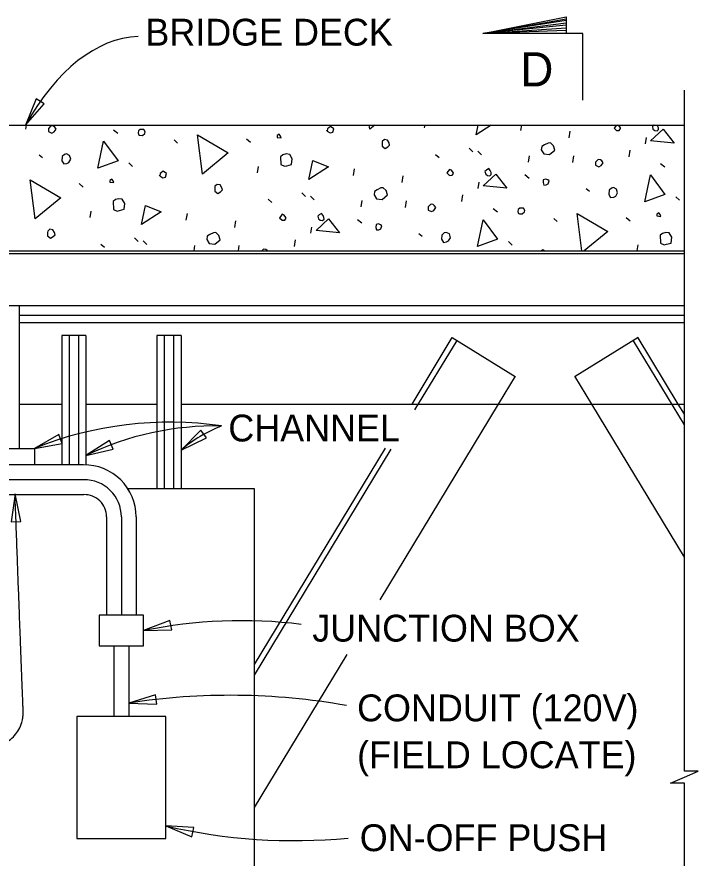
# Model space of a CAD drawing. Extents: x 927736.2 to 927809.6, y 636703.6 to 636757.7.
# Drawn here: x 927764.73 to 927774.19, y 636721.33 to 636733.02 of the extents above; entities that cross this region are included whole.
import ezdxf

# ---------------------------------------------------------------- set-up
doc = ezdxf.new("R2010")
doc.units = 0
for name, color, linetype in [('DimLines_dp', 7, 'Continuous'), ('Miscellaneous1', 7, 'Continuous'), ('Miscellaneous2', 7, 'Continuous'), ('Miscellaneous3', 7, 'Continuous')]:
    doc.layers.add(name, color=color, linetype=linetype)

msp = doc.modelspace()

# ---------------------------------------------------------------- linework, layer by layer
at = {"layer": 'DimLines_dp'}
for p, q in [((927771.201, 636732.786), (927772.357, 636732.99)), ((927772.357, 636732.965), (927771.201, 636732.786)), ((927771.201, 636732.786), (927772.357, 636732.934)), ((927772.357, 636732.901), (927771.201, 636732.786)), ((927771.201, 636732.786), (927772.357, 636732.867)), ((927772.357, 636732.83), (927771.201, 636732.786))]:
    msp.add_line(p, q, dxfattribs=at)
for points in [[(927772.589, 636731.861), (927772.589, 636732.786), (927771.201, 636732.786), (927772.357, 636733.018), (927772.357, 636732.786)], [(927774, 636713.104), (927774, 636722.378), (927773.809, 636722.378), (927774, 636722.461), (927774.191, 636722.544), (927774, 636722.544), (927774, 636731.999)]]:
    msp.add_lwpolyline(points, dxfattribs=at)
for points in [[(927764.852, 636731.515), (927765.11, 636731.808), (927764.999, 636731.877)], [(927767.01, 636727), (927767.362, 636727.17), (927767.286, 636727.277)], [(927764.974, 636727.024), (927765.359, 636727.094), (927765.315, 636727.216)], [(927765.688, 636726.926), (927766.068, 636727.016), (927766.018, 636727.136)], [(927764.705, 636726.393), (927764.654, 636726.006), (927764.785, 636726.011)], [(927766.491, 636724.495), (927766.881, 636724.507), (927766.855, 636724.635)], [(927766.285, 636723.488), (927766.675, 636723.474), (927766.658, 636723.603)], [(927766.799, 636721.782), (927767.159, 636721.632), (927767.189, 636721.759)]]:
    msp.add_lwpolyline(points, close=True, dxfattribs=at)
for centre, radius, start, end in [((927766.848, 636722.389), 5, 81.6635, 112.0069), ((927767.492, 636723.175), 4.162, 88.8828, 115.6789), ((927768.324, 636725.436), 2.043, 111.5678, 130.0212), ((927767.852, 636717.791), 6.841, 83.0445, 101.4782), ((927767.692, 636714.325), 9.271, 79.9649, 98.7311), ((927768.59, 636729.517), 7.939, 256.9627, 275.3449)]:
    msp.add_arc(centre, radius, start, end, dxfattribs=at)
msp.add_ellipse((927766.69, 636726.905), major_axis=(0.274, -5.84), ratio=0.464296, start_param=3.141604, end_param=3.781059, dxfattribs=at)
msp.add_open_spline([(927758.883, 636722.628), (927762.516, 636722.653), (927764.844, 636722.779), (927764.793, 636724), (927764.705, 636726.393)], degree=2, dxfattribs=at)
at = {"layer": 'Miscellaneous1'}
for p, q in [((927765.354, 636728.592), (927765.354, 636726.795)), ((927765.688, 636728.592), (927765.354, 636728.592)), ((927765.457, 636728.592), (927765.457, 636726.795)), ((927765.586, 636728.592), (927765.586, 636726.795)), ((927765.688, 636728.592), (927765.688, 636726.795)), ((927767.01, 636728.592), (927766.676, 636728.592)), ((927766.676, 636728.592), (927766.676, 636726.463)), ((927766.778, 636728.592), (927766.778, 636726.463)), ((927766.907, 636728.592), (927766.907, 636726.463)), ((927767.01, 636728.592), (927767.01, 636726.463)), ((927764.139, 636727.024), (927764.974, 636727.024)), ((927764.974, 636727.024), (927764.974, 636726.795)), ((927765.656, 636726.795), (927764.242, 636726.795)), ((927765.66, 636726.589), (927764.242, 636726.59)), ((927764.242, 636726.384), (927765.662, 636726.383)), ((927765.976, 636726.075), (927765.976, 636724.707)), ((927766.182, 636726.075), (927766.182, 636724.707)), ((927766.388, 636726.075), (927766.388, 636724.707)), ((927766.079, 636724.283), (927766.079, 636723.302)), ((927766.285, 636724.283), (927766.285, 636723.302))]:
    msp.add_line(p, q, dxfattribs=at)
for points in [[(927766.49, 636724.707), (927765.874, 636724.707), (927765.874, 636724.283), (927766.49, 636724.283)], [(927766.799, 636723.302), (927765.565, 636723.302), (927765.565, 636721.607), (927766.799, 636721.607)]]:
    msp.add_lwpolyline(points, close=True, dxfattribs=at)
for radius, end in [(0.72, 90.9434), (0.514, 90.8699), (0.308, 91.129)]:
    msp.add_arc((927765.668, 636726.075), radius, 0, end, dxfattribs=at)
at = {"layer": 'Miscellaneous2'}
for p, q in [((927753.063, 636731.515), (927774, 636731.515)), ((927764.855, 636731.46), (927764.863, 636731.515)), ((927770.393, 636731.476), (927770.399, 636731.515)), ((927771.731, 636731.438), (927771.742, 636731.515)), ((927766.072, 636731.448), (927766.135, 636731.401)), ((927772.402, 636731.337), (927772.416, 636731.43)), ((927773.458, 636731.256), (927773.473, 636731.343)), ((927766.913, 636731.309), (927766.963, 636731.265)), ((927767.918, 636731.323), (927767.976, 636731.275)), ((927765.041, 636731.101), (927765.089, 636731.063)), ((927770.542, 636731.107), (927770.593, 636731.063)), ((927771.011, 636731.194), (927771.062, 636731.144)), ((927771.131, 636731.15), (927771.183, 636731.1)), ((927773.232, 636731.075), (927773.246, 636731.168)), ((927766.284, 636730.988), (927766.336, 636730.938)), ((927771.835, 636731), (927771.85, 636731.087)), ((927772.45, 636730.993), (927772.463, 636731.086)), ((927768.07, 636730.853), (927768.085, 636730.94)), ((927769.407, 636730.816), (927769.421, 636730.909)), ((927773.666, 636730.98), (927773.73, 636730.933)), ((927770.079, 636730.715), (927770.093, 636730.808)), ((927771.786, 636730.827), (927771.843, 636730.779)), ((927765.595, 636730.701), (927765.653, 636730.652)), ((927771.135, 636730.634), (927771.15, 636730.721)), ((927772.636, 636730.634), (927772.684, 636730.596)), ((927768.688, 636730.572), (927768.739, 636730.522)), ((927768.808, 636730.528), (927768.86, 636730.478)), ((927770.909, 636730.452), (927770.923, 636730.545)), ((927773.879, 636730.52), (927773.931, 636730.47)), ((927768.219, 636730.485), (927768.269, 636730.441)), ((927769.512, 636730.378), (927769.527, 636730.465)), ((927770.127, 636730.37), (927770.14, 636730.463)), ((927765.747, 636730.231), (927765.762, 636730.318)), ((927767.084, 636730.193), (927767.098, 636730.286)), ((927771.343, 636730.358), (927771.407, 636730.311)), ((927767.756, 636730.092), (927767.77, 636730.185)), ((927769.463, 636730.205), (927769.52, 636730.157)), ((927772.185, 636730.219), (927772.235, 636730.175)), ((927773.19, 636730.233), (927773.247, 636730.185)), ((927768.812, 636730.012), (927768.827, 636730.099)), ((927766.365, 636729.949), (927766.416, 636729.899)), ((927770.313, 636730.011), (927770.361, 636729.973)), ((927765.896, 636729.862), (927765.946, 636729.818)), ((927766.485, 636729.905), (927766.537, 636729.855)), ((927767.191, 636729.768), (927767.204, 636729.842)), ((927767.807, 636729.768), (927767.817, 636729.841)), ((927768.586, 636729.83), (927768.6, 636729.923)), ((927771.556, 636729.898), (927771.608, 636729.848)), ((927773.342, 636729.768), (927773.356, 636729.85)), ((927762.11, 636729.768), (927774, 636729.768)), ((927762.121, 636729.73), (927774, 636729.73)), ((927760.453, 636729.01), (927774, 636729.01))]:
    msp.add_line(p, q, dxfattribs=at)
for points in [[(927765.172, 636731.469), (927765.171, 636731.424), (927765.215, 636731.403), (927765.249, 636731.419), (927765.277, 636731.458), (927765.257, 636731.485), (927765.241, 636731.5), (927765.213, 636731.505), (927765.202, 636731.502), (927765.172, 636731.469)], [(927766.421, 636731.382), (927766.436, 636731.373), (927766.475, 636731.371), (927766.506, 636731.398), (927766.513, 636731.419), (927766.492, 636731.452), (927766.441, 636731.451), (927766.42, 636731.433), (927766.415, 636731.406), (927766.421, 636731.382)], [(927769.038, 636731.432), (927769.083, 636731.406), (927769.119, 636731.415), (927769.132, 636731.463), (927769.085, 636731.495), (927769.064, 636731.477), (927769.042, 636731.465), (927769.038, 636731.432), (927769.035, 636731.444)], [(927769.632, 636731.457), (927769.624, 636731.515)], [(927769.702, 636731.515), (927769.632, 636731.457)], [(927771.108, 636731.38), (927771.137, 636731.515)], [(927771.318, 636731.515), (927771.108, 636731.38)], [(927773.024, 636731.472), (927773.059, 636731.437), (927773.096, 636731.44), (927773.115, 636731.465), (927773.112, 636731.476), (927773.091, 636731.509), (927773.075, 636731.515)], [(927773.058, 636731.515), (927773.043, 636731.496), (927773.024, 636731.472)], [(927773.531, 636731.295), (927773.705, 636731.457), (927773.859, 636731.262), (927773.531, 636731.295)], [(927773.581, 636731.515), (927773.575, 636731.511), (927773.555, 636731.493), (927773.564, 636731.457)], [(927773.564, 636731.457), (927773.588, 636731.438), (927773.621, 636731.434), (927773.642, 636731.452), (927773.642, 636731.478), (927773.628, 636731.506), (927773.621, 636731.515)], [(927767.308, 636730.834), (927767.24, 636731.378), (927767.664, 636731.128), (927767.308, 636730.834)], [(927768.347, 636731.342), (927768.399, 636731.337), (927768.393, 636731.361), (927768.373, 636731.388), (927768.347, 636731.368), (927768.347, 636731.342)], [(927765.856, 636730.918), (927765.935, 636731.29), (927766.136, 636731.018), (927765.856, 636730.918)], [(927769.804, 636731.267), (927769.803, 636731.222), (927769.844, 636731.188), (927769.882, 636731.211), (927769.907, 636731.237), (927769.9, 636731.267), (927769.876, 636731.305), (927769.836, 636731.314), (927769.805, 636731.286), (927769.804, 636731.267)], [(927772.013, 636731.169), (927772.047, 636731.115), (927772.127, 636731.104), (927772.199, 636731.168), (927772.183, 636731.228), (927772.14, 636731.267), (927772.109, 636731.265), (927772.058, 636731.239), (927772.02, 636731.216), (927772.013, 636731.169)], [(927765.36, 636731.078), (927765.356, 636731.02), (927765.381, 636730.975), (927765.424, 636730.981), (927765.452, 636730.995), (927765.479, 636731.04), (927765.464, 636731.094), (927765.421, 636731.114), (927765.391, 636731.106), (927765.36, 636731.078)], [(927768.393, 636731.074), (927768.397, 636730.966), (927768.448, 636730.942), (927768.478, 636730.95), (927768.543, 636730.967), (927768.554, 636731.047), (927768.519, 636731.108), (927768.472, 636731.114), (927768.424, 636731.101), (927768.393, 636731.074)], [(927768.785, 636730.757), (927768.842, 636731.022), (927769.057, 636730.933), (927768.785, 636730.757)], [(927772.767, 636731.001), (927772.766, 636730.956), (927772.81, 636730.936), (927772.844, 636730.951), (927772.872, 636730.991), (927772.852, 636731.017), (927772.835, 636731.032), (927772.808, 636731.038), (927772.796, 636731.034), (927772.767, 636731.001)], [(927766.715, 636730.809), (927766.76, 636730.783), (927766.796, 636730.793), (927766.809, 636730.841), (927766.762, 636730.873), (927766.741, 636730.855), (927766.719, 636730.842), (927766.715, 636730.809), (927766.712, 636730.821)], [(927770.701, 636730.85), (927770.736, 636730.814), (927770.773, 636730.818), (927770.792, 636730.842), (927770.789, 636730.854), (927770.768, 636730.887), (927770.739, 636730.898), (927770.72, 636730.874), (927770.701, 636730.85)], [(927771.241, 636730.835), (927771.265, 636730.816), (927771.298, 636730.812), (927771.319, 636730.83), (927771.319, 636730.855), (927771.305, 636730.884), (927771.285, 636730.91), (927771.252, 636730.889), (927771.231, 636730.87), (927771.241, 636730.835)], [(927764.985, 636730.212), (927764.916, 636730.755), (927765.341, 636730.505), (927764.985, 636730.212)], [(927766.024, 636730.72), (927766.076, 636730.715), (927766.07, 636730.739), (927766.05, 636730.765), (927766.024, 636730.745), (927766.024, 636730.72)], [(927771.208, 636730.673), (927771.382, 636730.834), (927771.536, 636730.639), (927771.208, 636730.673)], [(927772.039, 636730.716), (927772.048, 636730.681), (927772.08, 636730.683), (927772.108, 636730.697), (927772.122, 636730.739), (927772.106, 636730.754), (927772.077, 636730.765), (927772.041, 636730.755), (927772.039, 636730.716)], [(927773.451, 636730.45), (927773.53, 636730.822), (927773.73, 636730.55), (927773.451, 636730.45)], [(927767.481, 636730.644), (927767.48, 636730.599), (927767.521, 636730.566), (927767.559, 636730.589), (927767.584, 636730.615), (927767.576, 636730.644), (927767.553, 636730.683), (927767.513, 636730.691), (927767.482, 636730.664), (927767.481, 636730.644)], [(927769.69, 636730.547), (927769.724, 636730.492), (927769.804, 636730.481), (927769.876, 636730.545), (927769.86, 636730.605), (927769.817, 636730.645), (927769.786, 636730.643), (927769.735, 636730.616), (927769.697, 636730.593), (927769.69, 636730.547)], [(927772.955, 636730.611), (927772.951, 636730.552), (927772.976, 636730.508), (927773.019, 636730.513), (927773.047, 636730.527), (927773.073, 636730.572), (927773.059, 636730.626), (927773.015, 636730.646), (927772.986, 636730.638), (927772.955, 636730.611)], [(927766.07, 636730.452), (927766.074, 636730.344), (927766.125, 636730.319), (927766.155, 636730.327), (927766.22, 636730.345), (927766.231, 636730.424), (927766.195, 636730.485), (927766.149, 636730.492), (927766.101, 636730.479), (927766.07, 636730.452)], [(927766.462, 636730.135), (927766.519, 636730.399), (927766.734, 636730.31), (927766.462, 636730.135)], [(927770.444, 636730.379), (927770.443, 636730.334), (927770.487, 636730.313), (927770.521, 636730.329), (927770.549, 636730.368), (927770.529, 636730.395), (927770.512, 636730.41), (927770.485, 636730.415), (927770.473, 636730.412), (927770.444, 636730.379)], [(927768.918, 636730.212), (927768.942, 636730.193), (927768.975, 636730.189), (927768.996, 636730.208), (927768.995, 636730.233), (927768.982, 636730.261), (927768.962, 636730.288), (927768.929, 636730.266), (927768.908, 636730.248), (927768.918, 636730.212)], [(927771.693, 636730.292), (927771.708, 636730.283), (927771.747, 636730.281), (927771.778, 636730.308), (927771.785, 636730.329), (927771.764, 636730.362), (927771.713, 636730.361), (927771.692, 636730.343), (927771.687, 636730.316), (927771.693, 636730.292)], [(927772.577, 636729.768), (927772.511, 636730.288), (927772.936, 636730.038), (927772.609, 636729.768)], [(927773.619, 636730.252), (927773.671, 636730.247), (927773.665, 636730.271), (927773.645, 636730.298), (927773.618, 636730.278), (927773.619, 636730.252)], [(927768.378, 636730.227), (927768.413, 636730.192), (927768.45, 636730.195), (927768.469, 636730.22), (927768.466, 636730.232), (927768.444, 636730.264), (927768.416, 636730.276), (927768.397, 636730.251), (927768.378, 636730.227)], [(927768.885, 636730.05), (927769.059, 636730.212), (927769.213, 636730.017), (927768.885, 636730.05)], [(927771.128, 636729.828), (927771.207, 636730.2), (927771.407, 636729.928), (927771.128, 636729.828)], [(927765.158, 636730.022), (927765.157, 636729.977), (927765.198, 636729.943), (927765.236, 636729.966), (927765.261, 636729.992), (927765.253, 636730.022), (927765.23, 636730.06), (927765.19, 636730.069), (927765.159, 636730.041), (927765.158, 636730.022)], [(927769.716, 636730.094), (927769.725, 636730.058), (927769.757, 636730.06), (927769.785, 636730.074), (927769.799, 636730.116), (927769.782, 636730.131), (927769.754, 636730.143), (927769.718, 636730.133), (927769.716, 636730.094)], [(927767.367, 636729.924), (927767.401, 636729.87), (927767.48, 636729.859), (927767.553, 636729.923), (927767.537, 636729.983), (927767.494, 636730.022), (927767.463, 636730.02), (927767.412, 636729.994), (927767.374, 636729.971), (927767.367, 636729.924)], [(927770.632, 636729.988), (927770.628, 636729.93), (927770.653, 636729.885), (927770.696, 636729.891), (927770.724, 636729.905), (927770.75, 636729.95), (927770.736, 636730.003), (927770.692, 636730.024), (927770.662, 636730.016), (927770.632, 636729.988)], [(927773.665, 636729.984), (927773.669, 636729.876), (927773.72, 636729.852), (927773.75, 636729.86), (927773.815, 636729.877), (927773.826, 636729.957), (927773.79, 636730.017), (927773.744, 636730.024), (927773.696, 636730.011), (927773.665, 636729.984)], [(927768.209, 636729.768), (927768.206, 636729.772), (927768.189, 636729.787), (927768.162, 636729.793), (927768.15, 636729.789), (927768.132, 636729.768)], [(927772.055, 636729.768), (927772.034, 636729.783), (927772.017, 636729.768)]]:
    msp.add_lwpolyline(points, dxfattribs=at)
at = {"layer": 'Miscellaneous3'}
for p, q in [((927764.769, 636727.024), (927764.769, 636729.01)), ((927764.769, 636728.875), (927774, 636728.875)), ((927764.769, 636728.772), (927774, 636728.772)), ((927770.219, 636727.641), (927770.777, 636728.564)), ((927770.777, 636728.564), (927771.65, 636728.021)), ((927773.356, 636728.564), (927772.483, 636728.021)), ((927773.915, 636727.641), (927773.36, 636728.559)), ((927770.259, 636727.559), (927770.843, 636728.524)), ((927774, 636727.351), (927773.294, 636728.519)), ((927771.42, 636727.641), (927771.654, 636728.027)), ((927772.713, 636727.641), (927772.48, 636728.027)), ((927764.769, 636727.641), (927765.354, 636727.641)), ((927765.688, 636727.641), (927766.676, 636727.641)), ((927767.01, 636727.641), (927774, 636727.641)), ((927769.775, 636724.921), (927771.42, 636727.641)), ((927774, 636725.514), (927772.713, 636727.641)), ((927774, 636727.5), (927773.915, 636727.641)), ((927768.032, 636724.026), (927769.848, 636727.028)), ((927768.032, 636723.877), (927769.929, 636727.014)), ((927768.032, 636722.04), (927769.316, 636724.163))]:
    msp.add_line(p, q, dxfattribs=at)
msp.add_lwpolyline([(927768.032, 636718.446), (927768.032, 636718.446), (927768.032, 636726.463), (927766.275, 636726.463)], dxfattribs=at)

# ---------------------------------------------------------------- texts
at = {"layer": 'DimLines_dp'}
for s, height, p in [('BRIDGE DECK', 0.37296, (927766.515, 636732.618)), ('D', 0.474, (927771.723, 636732.052)), ('CHANNEL', 0.373, (927767.667, 636727.121)), ('JUNCTION BOX', 0.37296, (927768.833, 636724.342)), ('CONDUIT (120V)', 0.37296, (927769.455, 636723.235)), ('(FIELD LOCATE)', 0.37296, (927769.455, 636722.584)), ('ON-OFF PUSH ', 0.37296, (927769.492, 636721.432))]:
    msp.add_text(s, height=height, dxfattribs=at).set_placement(p)

doc.saveas('drawing.dxf')
